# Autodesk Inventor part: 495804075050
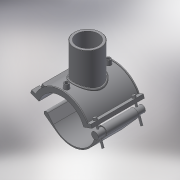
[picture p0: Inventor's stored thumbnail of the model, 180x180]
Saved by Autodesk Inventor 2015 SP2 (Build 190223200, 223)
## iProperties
Created: 2017-07
Part Number: 495804075050
Material: Generic
Description: PLASSON BRANCH SADDLE 75-50
Document SubType Name: Modeling
Designer: KIM
Density: 1 g/cm^3
Appearance: Default
Author: KIM
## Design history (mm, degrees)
derived "495804.ipt"
feature "Solid1::495804.ipt"
feature "Solid2::495804.ipt"
tag "TaggingFeature1"
body "Solid1"
body "Solid2"
other parameters: "d0" = 75, "d2" = 117, "d3" = 18.75, "d4" = 118, "d5" = 0, "d6" = 0.1, "d8" = 0, "d19" = 6, "d20" = 6, "d21" = 70.8, "d23" = 0, "d24" = 35.4, "d26" = 0, "d27" = 3, "d28" = 3, "d29" = 3, "d30" = 25, "d31" = 6, "d32" = 0, "d33" = 0, "d34" = 0.6, "d40" = 50.44, "d41" = 55, "d43" = 0, "d45" = 0, "d47" = 141.5, "d50" = 0, "d70" = 15, "d72" = 0, "d73" = 6, "d75" = 5, "d76" = 0, "d77" = 3.75, "d78" = 67.5, "d79" = 15, "d80" = 47.2, "d82" = 5 deg, "d84" = 4, "d85" = 14, "d86" = 0, "d87" = 3, "d88" = 0, "d89" = 1, "d90" = 1, "d91" = 94.4, "d92" = 0, "d93" = 0.5, "d94" = 39.47368, "d96" = 98.94, "d97" = 2.36, "d98" = 0, "d102" = 1.5, "d105" = 0, "d109" = -31, "d117" = 0.5, "d120" = 140 deg, "d121" = 24.228, "d122" = 20 deg, "d123" = 194, "d124" = 58.2, "d126" = 0, "d143" = 78.75, "d150" = 13.5, "d159" = 4.4, "d161" = 1.875, "d162" = 70.8, "d163" = 0, "d167" = 15, "d168" = 44.09091, "d173" = 1, "d175" = 37.5, "d176" = 20 deg, "d177" = 5.25, "d178" = 22, "d180" = 0, "d185" = 38.35, "d186" = 38.35, "d187" = 48.5, "d188" = 6.6, "d189" = 5.25, "d190" = 0, "d191" = 72.75, "d200" = 11, "d202" = 0, "d216" = 106.2, "d217" = 0, "d221" = 43.66, "d222" = 5.25, "d223" = 3.15, "d224" = 37.5, "d225" = 3.15, "d227" = 10.8, "d230" = 46.5, "d236" = 20 deg, "d237" = 55.5, "d238" = 20 deg, "d239" = 5.25, "d_" = 75, "B_" = 117, "H_" = 93, "L_" = 118, "d_t" = 6, "H_1" = 82, "d1" = 97, "d148" = 1.875, "d160" = 1.875
